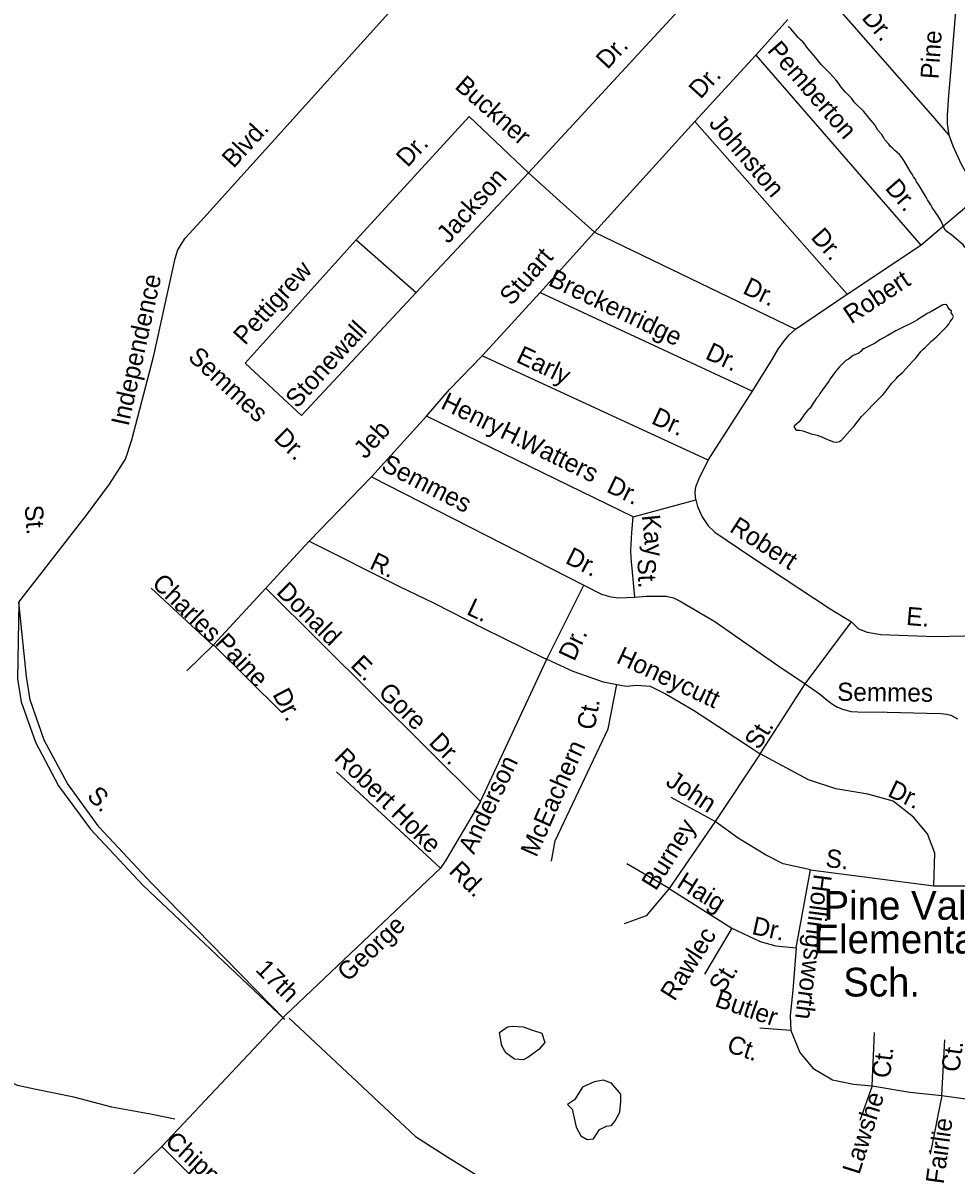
# Model space of a CAD drawing. Extents: x 2290055 to 2389491, y 66597 to 237875.
# Drawn here: x 2327683 to 2332561, y 156845 to 162814 of the extents above; entities that cross this region are included whole.
import ezdxf

# ---------------------------------------------------------------- set-up
doc = ezdxf.new("R2010")
doc.units = 0
for name, color, linetype in [('Exist Cultural Educational Facility Elementary Label', 7, 'Continuous'), ('Exist Hydrographic Creek Single Shore', 7, 'Continuous'), ('Exist Hydrographic Pond Under 1500 Sq Ft', 7, 'Continuous'), ('Exist Road Non-System Type 51', 7, 'Continuous'), ('Exist Road Non-System Type 51 Label', 7, 'Continuous')]:
    doc.layers.add(name, color=color, linetype=linetype)

msp = doc.modelspace()

# ---------------------------------------------------------------- linework, layer by layer
at = {"layer": 'Exist Hydrographic Creek Single Shore'}
for points in [[(2332480.2, 161781.4), (2332470, 161797.9), (2332436, 161848.8), (2332428.2, 161862.7), (2332411.5, 161889.1), (2332404.5, 161903), (2332379.7, 161943.6), (2332363.5, 161969.8), (2332354.2, 161982.8), (2332347.5, 161996.7), (2332338.5, 162009.5), (2332330.5, 162023.2), (2332321.5, 162035.7), (2332290.7, 162089), (2332274, 162114.8), (2332264.2, 162126.6), (2332240.2, 162146), (2332230, 162157.3), (2332217.5, 162167.2), (2332208.5, 162179.7), (2332188, 162203.2), (2332181.5, 162217), (2332172.5, 162229.5), (2332152.2, 162253.5), (2332135.5, 162280.2), (2332106, 162315.5), (2332087.7, 162340.8), (2332076.5, 162352.2), (2332041.5, 162384.6), (2332030.7, 162395.8), (2332013, 162420.5), (2331980.2, 162453.9), (2331960, 162477.7), (2331941.5, 162502.9), (2331931.5, 162515), (2331901, 162550), (2331857.5, 162594.7), (2331818, 162642), (2331797.2, 162664.9), (2331778, 162689.1), (2331769, 162702.4), (2331759, 162713.7), (2331747.2, 162724), (2331736.5, 162734.7), (2331717.2, 162758.7), (2331706.5, 162769.9), (2331696.5, 162781.9), (2331685.2, 162791.9), (2331684.5, 162793.9)], [(2332816.2, 161478.5), (2332790.2, 161477.2), (2332753, 161493.1), (2332737.2, 161510.5), (2332724.5, 161519.4), (2332711, 161526.9), (2332673.7, 161555.5), (2332663, 161566.7), (2332644.5, 161590.9), (2332637.2, 161604.4), (2332628.7, 161617.6), (2332606.5, 161641.2), (2332596.7, 161653), (2332538.2, 161704.2), (2332514.2, 161721.3), (2332504, 161730.8), (2332480.2, 161781.4)]]:
    msp.add_lwpolyline(points, dxfattribs=at)
at = {"layer": 'Exist Hydrographic Pond Under 1500 Sq Ft'}
for points in [[(2331935.5, 160623.5), (2331950.2, 160626.2), (2331963.2, 160635.7), (2332016.5, 160695.6), (2332027.5, 160706.9), (2332036.5, 160719.1), (2332065.5, 160756.8), (2332088.5, 160778.7), (2332133.2, 160825.7), (2332178, 160870.8), (2332188, 160882.2), (2332225.2, 160931.9), (2332247, 160954), (2332256.7, 160966.6), (2332281.5, 160988.9), (2332313.5, 161023.2), (2332334, 161046.6), (2332346, 161058.1), (2332356.7, 161070.6), (2332375.5, 161096), (2332386.7, 161106.8), (2332399.2, 161117.3), (2332432.5, 161150.6), (2332457, 161171.3), (2332469, 161182.9), (2332512, 161227.6), (2332522, 161240), (2332530, 161253.3), (2332540, 161265.1), (2332546.2, 161279.1), (2332542.2, 161289.6), (2332535, 161298.4), (2332536.2, 161308.5), (2332528.5, 161314), (2332519, 161326), (2332512, 161339.4), (2332506.5, 161342.1), (2332491.7, 161340.4), (2332424.2, 161302.4), (2332410, 161295.3), (2332397.5, 161286.7), (2332370.7, 161271.1), (2332358, 161262), (2332330.2, 161245.8), (2332273.5, 161217.8), (2332244.7, 161204.6), (2332204, 161179.4), (2332162.7, 161157.3), (2332137.5, 161140.5), (2332082.5, 161111.9), (2332078.5, 161110), (2332073.5, 161109.8), (2332063.7, 161097.6), (2332051.5, 161088.2), (2332023.2, 161074.9), (2331998, 161056.7), (2331984.5, 161048.8), (2331972.5, 161038.1), (2331962.2, 161026.6), (2331950.2, 161016), (2331930, 160991.7), (2331903, 160954.2), (2331895, 160941), (2331848.5, 160877.4), (2331840.5, 160863.8), (2331830, 160852.6), (2331822.5, 160838.4), (2331813.7, 160826.2), (2331797.7, 160800.3), (2331786.2, 160790.3), (2331766.5, 160766.9), (2331758.5, 160753.3), (2331748.5, 160741.5), (2331740, 160729.1), (2331716.7, 160708.8), (2331712.7, 160704.3), (2331720.7, 160691.5), (2331728, 160685.1), (2331743.2, 160684.8), (2331759, 160682.2), (2331788.5, 160671), (2331803.2, 160666.4), (2331833.7, 160659.2), (2331848.2, 160654.4), (2331862, 160648.7), (2331876.2, 160641.7), (2331905, 160629.8), (2331919.5, 160625.3), (2331935.5, 160623.5)], [(2330174.7, 157538.9), (2330215.6, 157567.5), (2330240.1, 157571.6), (2330297.2, 157567.5), (2330346.2, 157551.2), (2330395.2, 157534.8), (2330411.5, 157485.8), (2330378.9, 157449), (2330321.7, 157408.1), (2330297.2, 157395.9), (2330252.3, 157400), (2330207.4, 157432.7), (2330187, 157469.4), (2330174.7, 157538.9)], [(2330607.5, 157252.9), (2330566.7, 157187.5), (2330529.9, 157163), (2330554.4, 157138.4), (2330574.8, 157044.4), (2330599.3, 156999.5), (2330632, 156979.1), (2330664.7, 156983.1), (2330697.3, 157032.2), (2330734.1, 157048.5), (2330758.6, 157052.6), (2330779, 157077.1), (2330803.5, 157122.1), (2330807.6, 157179.3), (2330807.6, 157216.1), (2330758.6, 157273.3), (2330717.7, 157289.6), (2330668.7, 157281.5), (2330607.5, 157252.9)]]:
    msp.add_lwpolyline(points, dxfattribs=at)
at = {"layer": 'Exist Road Non-System Type 51'}
for p, q in [((2330325.7, 162030), (2331381, 163172.2)), ((2331680.8, 162830.3), (2331513.7, 162645.4)), ((2331513.7, 162645.4), (2331195.3, 162298.7)), ((2331513.7, 162645.4), (2332375.4, 161652.9)), ((2331195.3, 162298.7), (2330670.1, 161719.6)), ((2331991.4, 161395.8), (2331195.3, 162298.7)), ((2330325.7, 162030), (2329738.3, 161404.5)), ((2330489.3, 161882.5), (2330325.7, 162030)), ((2330670.1, 161719.6), (2330489.3, 161882.5)), ((2332518, 161772.5), (2332683.2, 161911.2)), ((2332375.4, 161652.9), (2332518, 161772.5)), ((2329425.1, 161680.2), (2329738.3, 161404.5)), ((2330386.5, 161404.2), (2330670.1, 161719.6)), ((2330670.1, 161719.6), (2331720.7, 161212.8)), ((2331991.4, 161395.8), (2332375.4, 161652.9)), ((2330083.5, 161074.2), (2330386.5, 161404.2)), ((2330386.5, 161404.2), (2331497.1, 160889.9)), ((2331720.7, 161212.8), (2331991.4, 161395.8)), ((2331265.3, 160528.9), (2330083.5, 161074.2)), ((2331265.3, 160528.9), (2331497.1, 160889.9)), ((2330873, 160233), (2329791.8, 160758.4)), ((2330873, 160233), (2331199.6, 160322.1)), ((2331771.6, 159360.1), (2332013.2, 159684.1))]:
    msp.add_line(p, q, dxfattribs=at)
for points in [[(2327661.6, 159787.7), (2328015.7, 160240.9), (2328136.2, 160403.3), (2328219.7, 160533.2), (2328252.1, 160635.2), (2328368, 161075.9), (2328479.3, 161582.1), (2328493.2, 161628.5), (2328530.3, 161688.8), (2328613.7, 161776.9), (2329642.9, 162918.1), (2329795.9, 163095.4), (2329860.8, 163216), (2329930.3, 163420.1), (2329953.5, 163666), (2329953.5, 163916.1)], [(2332585.5, 163219.8), (2332534.1, 162595.5), (2332519.3, 162413.1), (2332515.8, 162352.9), (2332514.6, 162332.8), (2332514.4, 162286.6), (2332522.6, 162229.1)], [(2332522.6, 162229.1), (2332438.4, 162325.2), (2331841.6, 163008.2)], [(2329425.1, 161680.2), (2330016, 162323.9), (2330325.7, 162030)], [(2332522.6, 162229.1), (2332542.9, 162171.8), (2332586.8, 162075.4), (2332636.1, 161989.4), (2332683.2, 161911.2)], [(2329738.3, 161404.5), (2329139.5, 160762.8), (2328844.5, 161035), (2329425.1, 161680.2)], [(2331497.1, 160889.9), (2331598.6, 161054), (2331630.6, 161109.4), (2331662.9, 161154.7), (2331687.7, 161183.6), (2331720.7, 161212.8)], [(2329791.8, 160758.4), (2329912.3, 160897.4), (2330083.5, 161074.2)], [(2329791.8, 160758.4), (2329504.3, 160441.1), (2330614.1, 159875.9)], [(2331199.6, 160322.1), (2331196.2, 160357.8), (2331200.9, 160390.1), (2331217.2, 160432.8), (2331265.3, 160528.9)], [(2329179.3, 160105.9), (2329504.3, 160441.1)], [(2331199.6, 160322.1), (2331208.9, 160286.4), (2331233, 160233.2), (2331265, 160186.5), (2331300.2, 160151.8), (2331487.4, 160025.3), (2331902.5, 159751.6), (2332013.2, 159684.1)], [(2330881.7, 159813.3), (2330861.4, 160018.6), (2330859.9, 160056.6), (2330866.4, 160150.7), (2330873, 160233)], [(2328952.1, 159860), (2329179.3, 160105.9)], [(2329179.3, 160105.9), (2329652.1, 159869.3), (2329832.9, 159781.2), (2330087.9, 159651.3), (2330407.8, 159493.5), (2330421.7, 159488.9)], [(2328678.6, 159558.5), (2328354.1, 159860)], [(2328678.6, 159563.1), (2328952.1, 159860)], [(2328952.1, 159860), (2330075.5, 158745.3)], [(2330421.7, 159488.9), (2330614.1, 159875.9)], [(2330614.1, 159875.9), (2330706.8, 159828.4), (2330755.6, 159814.2), (2330797.8, 159810), (2330881.7, 159813.3)], [(2327661.6, 159787.7), (2327655.6, 159386.8), (2327674.2, 159266.1), (2327748.3, 159055.1), (2327868.9, 158827.7), (2328035.7, 158600.4), (2328309.3, 158308.2), (2329052.6, 157606.7), (2328356, 158319.4), (2328082.4, 158611.6), (2327915.6, 158839), (2327795, 159066.3), (2327720.8, 159277.4), (2327702.3, 159398), (2327661.6, 159787.7)], [(2330881.7, 159813.3), (2330939.3, 159817.5), (2330997.4, 159817.9), (2331045.6, 159817.8), (2331083.7, 159809.1), (2331118.5, 159792.5), (2331298.6, 159685.7), (2331628, 159456.5), (2331771.6, 159360.1)], [(2332013.2, 159684.1), (2332050.4, 159647.5), (2332095.4, 159629.3), (2332167.8, 159618), (2332450.4, 159607.2), (2332678, 159612.3), (2332728.2, 159612.3), (2332779.1, 159588.4), (2332820.4, 159555.9), (2332877.6, 159478.1), (2333030, 159217.9), (2333106.1, 159111), (2333135.1, 159084.2), (2333162, 159067.2), (2333190.3, 159058.2), (2333299.2, 159034.6)], [(2328539.5, 159428.6), (2328678.6, 159563.1)], [(2329035.6, 159210.6), (2328678.6, 159563.1)], [(2330075.5, 158745.3), (2330421.7, 159488.9)], [(2330421.7, 159488.9), (2330558, 159426.7), (2330715.6, 159371.1), (2330836.1, 159347.9), (2330891.8, 159352.5), (2330961.3, 159347.9), (2331044.7, 159306.1), (2331188.5, 159222.6), (2331494.4, 159023.1), (2331536.1, 158995.3)], [(2330446.4, 158433.7), (2330464.9, 158539.8), (2330741.4, 159125.6), (2330786.6, 159357.4)], [(2331536.1, 158995.3), (2331771.6, 159360.1)], [(2331771.6, 159360.1), (2331845.9, 159307.3), (2331895.4, 159267.2), (2331920.1, 159250.2), (2331940.5, 159238.8), (2331971.2, 159226.3), (2332011.7, 159215.7), (2332047.6, 159213.2), (2332199.9, 159211.3), (2332408.2, 159207.4), (2332480.2, 159204.4), (2332512.4, 159201.4), (2332532.7, 159196.3), (2332567.2, 159177.6)], [(2331536.1, 158995.3), (2331300.9, 158641.3), (2331061.3, 158290.8), (2330941.4, 158147.8), (2330826.2, 158106.3)], [(2332448.6, 158475.2), (2332411.7, 158576.7), (2332338, 158664.4), (2332232, 158747.4), (2332098.3, 158784.3), (2331932.4, 158811.9), (2331789.5, 158858.1), (2331536.1, 158995.3)], [(2329321.8, 158899.6), (2329865.7, 158396.8)], [(2331300.9, 158641.3), (2331070.5, 158765.8)], [(2330075.5, 158745.3), (2329893.3, 158438.3), (2329865.7, 158396.8), (2329057.4, 157631)], [(2331061.3, 158290.8), (2331388.5, 158083.2), (2331536, 158014), (2331619, 157991), (2331725, 157981.7), (2331798.7, 158387.6), (2331655.8, 158419.9), (2331563.6, 158466), (2331420.8, 158553.7), (2331300.9, 158641.3)], [(2331798.7, 158387.6), (2332444, 158304.6), (2332448.6, 158475.2)], [(2331061.3, 158290.8), (2330840, 158419.9)], [(2328476.6, 157085.3), (2328359.4, 157110.6), (2328147.9, 157148.2), (2327949.9, 157200.4), (2327744.1, 157242.1), (2327655.4, 157260.9), (2327618.5, 157279.5), (2327576.5, 157329.7), (2327542.5, 157384.5), (2327504, 157445), (2327427, 157524), (2327324.3, 157589.8), (2327077.4, 157758.3), (2326962.8, 157827.6), (2326861.7, 157901.7), (2326772.1, 157994), (2326694.1, 158089), (2326556.4, 158285.8)], [(2332444, 158304.6), (2332611.9, 158305.1)], [(2331388.5, 158083.2), (2331245.6, 157843.4)], [(2331725, 157981.7), (2331706.5, 157760.3), (2331692.7, 157626.6), (2331697.3, 157548.2), (2331743.4, 157434.7), (2331812.5, 157351.7), (2331913.9, 157291.7), (2332024.6, 157268.7), (2332121.3, 157259.5), (2332319.5, 157227.2), (2332485.5, 157208.7), (2332660.6, 157185.7), (2332817.3, 157167.2), (2333057, 157134.9), (2333112.3, 157559.3), (2333150.9, 157880.4)], [(2328409, 156943), (2329057.4, 157631)], [(2329074.5, 157614.2), (2329735.5, 156994.4), (2329904, 156887), (2330064.9, 156787.4), (2330306.6, 156694.5), (2332978.6, 156610), (2333405, 156611), (2333711.5, 156626.4), (2334109.8, 156703), (2334497.5, 156778.2), (2334742.6, 156808.8), (2335033.7, 156816.5), (2335352.2, 156786.3)], [(2331697.3, 157548.2), (2331534.3, 157561.7)], [(2332121.3, 157259.5), (2332133.3, 157538.7)], [(2332485.5, 157208.7), (2332501.1, 157500.3)], [(2332121.3, 157259.5), (2332056.7, 157078.7)], [(2332485.5, 157208.7), (2332424.5, 156902.4)], [(2327858.9, 156406.5), (2328409, 156943), (2328816.6, 156535.2), (2328956.6, 156414.2), (2329039.4, 156388.7), (2329205, 156318.6), (2329370.5, 156293.1), (2329497.9, 156274), (2329676.2, 156254.9), (2329886.3, 156203.9), (2330090.1, 156101.9), (2330306.6, 155980.8), (2330489.7, 155821.3)]]:
    msp.add_lwpolyline(points, dxfattribs=at)

# ---------------------------------------------------------------- texts
at = {"layer": 'Exist Cultural Educational Facility Elementary Label'}
for s, p in [('Pine Valley', (2331867.9, 158127.5)), ('Elementary', (2331814.9, 157951.3)), ('Sch.', (2331970.4, 157726.6))]:
    msp.add_text(s, height=150, dxfattribs=at).set_placement(p)
at = {"layer": 'Exist Road Non-System Type 51 Label'}
for s, rotation, p in [('Dr.', 310.75517, (2332062.9, 162837.9)), ('Pine', 86.06382, (2332468.5, 162517.5)), ('Dr.', 47.02913, (2330738.2, 162566.4)), ('Pemberton', 310.96572, (2331569.8, 162667.6)), ('Buckner', 318.75699, (2329935.2, 162475.3)), ('Dr.', 47.72459, (2331224.5, 162411.2)), ('Blvd.', 47.39813, (2328783.8, 162049.8)), ('Johnston', 310.46722, (2331264.2, 162286.1)), ('Dr.', 46.93132, (2329693.3, 162054.7)), ('Jackson', 47.94078, (2329906.5, 161655.6)), ('Dr.', 310.96572, (2332185.1, 161948)), ('Dr.', 311.4057, (2331796.9, 161690.8)), ('Stuart', 48.75828, (2330236.8, 161331.7)), ('Pettigrew', 47.76209, (2328844.2, 161124.7)), ('Independence', 77.6615, (2328235.2, 160702.8)), ('Breckenridge', 334.44387, (2330423.2, 161445.1)), ('Robert', 33.60339, (2332012.5, 161237.6)), ('Dr.', 334.24517, (2331439.8, 161402.9)), ('Stonewall', 47.70525, (2329116.4, 160795.3)), ('Dr.', 335.15116, (2331244.2, 161061.2)), ('Semmes', 317.29839, (2328540.6, 161060.1)), ('Early', 334.43428, (2330255.2, 161044.8)), ('Henry', 334.08535, (2329861.7, 160802)), ('Dr.', 335.22907, (2330962.3, 160722.8)), ('H.', 334.08535, (2330170.4, 160648.9)), ('Dr.', 315.67929, (2328988.9, 160639)), ('Jeb', 48.06486, (2329473, 160530.5)), ('Watters', 334.08535, (2330267.2, 160600.4)), ('Semmes', 333.00638, (2329549.6, 160478.5)), ('Dr.', 334.08535, (2330727.9, 160366.2)), ('St.', 274.32752, (2327692.1, 160291)), ('Kay', 275.63643, (2330917.9, 160239.8)), ('Robert', 327.16752, (2331370.8, 160159.1)), ('Dr.', 333.00638, (2330512.4, 159993.9)), ('R.', 334.80044, (2329489.2, 159965.1)), ('St.', 272.26869, (2330894.7, 160012.9)), ('Charles', 315.43929, (2328352, 159878.3)), ('Donald', 315.3708, (2329002.8, 159834.6)), ('L.', 334.86235, (2329996.7, 159725.5)), ('E.', 355.1231, (2332297, 159668.4)), ('Paine', 313.56631, (2328682.4, 159569.9)), ('Dr.', 64.80339, (2330564.6, 159473.4)), ('Honeycutt', 334.95456, (2330778.8, 159472.5)), ('E.', 315.3708, (2329390.3, 159452.1)), ('Gore', 315.3708, (2329535.2, 159309)), ('Semmes', 359.36399, (2331938.3, 159271.7)), ('Dr.', 297.78376, (2328985.5, 159305.9)), ('Ct.', 79.73178, (2330670.5, 159114.9)), ('St.', 57.91566, (2331528.8, 159010.8)), ('Dr.', 314.5535, (2329799.8, 159049.5)), ('McEachern', 66.26237, (2330366.8, 158449.7)), ('Robert Hoke', 315.44164, (2329304.5, 158967.4)), ('Anderson', 64.56382, (2330040, 158464.7)), ('John', 326.63824, (2331036.6, 158834.1)), ('S.', 314.61462, (2328013.1, 158769)), ('Dr.', 334.69141, (2332196.9, 158775.6)), ('Burney', 57.91566, (2330990.9, 158274.6)), ('S.', 352.8888, (2331874.5, 158404.3)), ('Rd.', 315.67732, (2329904.9, 158376.3)), ('Haig', 328.15287, (2331094.7, 158301.6)), ('Hollingsworth', 262.57798, (2331817.3, 158369.7)), ('George', 43.26424, (2329380.8, 157799.2)), ('Dr.', 347.6672, (2331488.6, 158053.5)), ('Rawlec', 57.77771, (2331088.8, 157697.4)), ('17th', 315.34354, (2328893.6, 157862.5)), ('St.', 57.77771, (2331342.6, 157737.3)), ('Butler', 341.19049, (2331294.2, 157676.9)), ('Ct.', 341.19049, (2331356.4, 157439.6)), ('Ct.', 83.1482, (2332214.2, 157296.5)), ('Ct.', 82.09702, (2332576.2, 157327.9)), ('Lawshe', 72.45931, (2332054.3, 156792)), ('Fairlie', 82.06908, (2332495, 156743.4)), ('Chippenham', 317.61757, (2328419.9, 156960.8))]:
    msp.add_text(s, height=95, rotation=rotation, dxfattribs=at).set_placement(p)

doc.saveas('drawing.dxf')
